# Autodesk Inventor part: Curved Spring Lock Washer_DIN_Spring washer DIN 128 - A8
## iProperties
Shininess: 64.0
Length Units: 11269
Angle Units: 11279
Time Units: 11290
Mass Units: 11283
Length Display Precision: 3
Angle Display Precision: 2
Compacted: True
Part Number: Curved Spring Lock Washer_DIN_Spring washer DIN 128 - A8
Document SubType Name: Modeling
Created: 2006-11
Material: Par défaut
Designer: profs_sti
Density: 0.0
Volumn: 0.0
Area: 0.0
PropertySet Name: Model Information
Control State: 0
Master: False
Checked Out: False
Author: profs_sti
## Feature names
1. Base1
